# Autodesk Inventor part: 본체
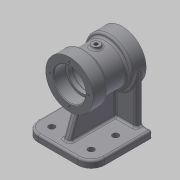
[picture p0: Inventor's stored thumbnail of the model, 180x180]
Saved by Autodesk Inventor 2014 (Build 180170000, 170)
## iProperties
Created: 2020-06
Part Number: 본체
Material: Generic
Document SubType Name: Modeling
Designer: kh
Density: 1 g/cm^3
Appearance: Default
Author: kh
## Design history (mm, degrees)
sketch "Sketch1"
  geometry: L1 (-49, -45)-(49, -45); L2 (49, -45)-(49, 45); L3 (49, 45)-(-49, 45); L4 (-49, 45)-(-49, -45); L5 (-49, -45)-(49, 45); L6 (49, -45)-(-49, 45); 1 further point
  constraints: 12 end point, 2 midpoint, 2 parallel, 1 horizontal, 1 perpendicular
  dimensions: "d0" = 98 distance of L2.end L3.end; "d1" = 90 distance of L1.end L2.end
extrude "Extrusion1" new body sketch "Sketch1" distance "d2" = 10; taper "d3" = 0 deg
workplane "Work Plane1"
sketch "Sketch2"
  geometry: L1 (49, 45)-(-49, 45) reference; L2 (-49, -45)-(49, -45) reference; L3 (0, 50)-(0, -70.604); L4 (0, 50)-(35, 50); L5 (35, 50)-(35, 28); L6 (35, 28)-(29, 28); L7 (29, 28)-(29, -6); L8 (29, -6)-(35, -6); L9 (35, -6)-(35, -28); L10 (35, -28)-(0, -28); 1 further point
  constraints: 16 end point, 5 perpendicular, 3 parallel, 1 midpoint, 1 point on line, 1 vertical alignment
  dimensions: "d5" = 5 distance from line of L1 L3.start; "d6" = 70 diameter of L5 L3; "d8" = 58 diameter of L7 L3; "d9" = 70 diameter of L9 L3; "d10" = 22 distance of L4.end L5.end; "d11" = 22 distance of L8.end L9.end; "d12" = 78 distance between parallel lines of L10 L4
revolve "Revolution1" sketch "Sketch2" stored, may be unused: angle "d13" = 90 deg
sketch "Sketch3"
  geometry: L1 (50, 115)-(50, 45) reference; L2 (-28, 115)-(-28, 45) reference; L3 (50, 80)-(-30.025, 80); L4 (50, 103.5)-(32, 103.5); L5 (32, 103.5)-(32, 100); L6 (32, 100)-(26, 100); L7 (26, 100)-(26, 103); L8 (26, 103)-(-4, 103); L9 (-4, 103)-(-4, 100); L10 (-4, 100)-(-10, 100); L11 (-10, 100)-(-10, 103.5); L12 (-10, 103.5)-(-28, 103.5); L13 (50, 103.5)-(50, 80); L14 (-28, 103.5)-(-28, 80)
  constraints: 24 end point, 7 parallel, 3 point on line, 2 collinear, 2 midpoint, 2 perpendicular
  dimensions: "d14" = 47 diameter of L4 L3; "d15" = 46 diameter of L8 L3; "d16" = 40 diameter of L6 L3; "d17" = 40 diameter of L10 L3; "d18" = 47 diameter of L12 L3; "d19" = 18 distance of L4.start L4.end; "d20" = 6 distance of L5.end L6.end; "d21" = 30 distance of L7.end L8.end; "d22" = 18 distance of L11.end L12.end
revolve "Revolution2" sketch "Sketch3" stored, may be unused: angle "d23" = 90 deg
sketch "Sketch4"
  geometry: L1 (49, 45)-(-49, 45) reference; L2 (-35, 45)-(35, 45); L3 (-35, 45)-(-35, 35); L4 (-35, 35)-(35, 35); L5 (35, 35)-(35, 45); 2 further points
  constraints: 8 end point, 2 midpoint, 2 perpendicular, 2 point on line, 1 coincident, 1 parallel
  dimensions: "d24" = 10 distance of L4.end L2.end; "d25" = 70 distance of L3.end L4.end
extrude "Extrusion2" join sketch "Sketch4" stored distance "d26" = 10; taper "d27" = 0 deg
sketch "Sketch5"
  geometry: L1 (-33, 10)-(-18.454, 49.965); L2 (45, 10)-(-45, 10) reference; L3 (-6, 45)-(-28, 45) reference
  constraints: 2 end point, 1 point on line
  dimensions: "d29" = 70 deg angle of L2 L1; "d89" = 12 distance of L2.end L1.start
feature "Rib1" sketch "Sketch5" dims "d30" = 1, "d31" = 10, "d32" = 0, "d33" = 0, "d34" = 1, "d35" = 1
sketch "Sketch6"
  geometry: C1 r 23.5 at (0, 0) reference; 1 further point
  constraints: 1 vertical alignment
  dimensions: "d36" = 28.5 distance of C1.centre point (0, -28.5)
hole "Hole1" sketch "Sketch6" at (0, -28.5) diameter "d37" = 3.242; stored, may be unused: countersink angle "d41" = 90 deg, drill point angle "d43" = 118 deg; dims "d38" = 10, "d39" = 4, "d40" = 2, "d42" = 12
pattern_circular "Circular Pattern1" dims angle "d45" = 360 deg
workplane "Work Plane2"
mirror "Mirror1"
workplane "Work Plane3"
sketch "Sketch7"
  geometry: L1 (-35, 39)-(35, 39) reference; C1 r 6 at (0, 0); 1 further point
  constraints: 1 centre point, 1 midpoint, 1 vertical alignment
  dimensions: "d47" = 39 distance from line of C1.centre L1; "d48" = 12 diameter of C1
extrude "Extrusion3" join sketch "Sketch7" stored distance "d49" = 6; taper "d50" = 0 deg
hole "Hole2" diameter "d53" = 5.188; stored, may be unused: countersink angle "d57" = 90 deg, drill point angle "d59" = 118 deg; dims "d51" = 10, "d52" = 10, "d54" = 10, "d55" = 4, "d56" = 2, "d58" = 12
sketch "Sketch8" dims "d14" = 47, "d15" = 46, "d16" = 40, "d17" = 40, "d18" = 47, "d19" = 18, "d20" = 6, "d21" = 30, "d22" = 18
  geometry: L1 (-49, 45)-(-49, -45) reference; L2 (49, -45)-(49, 45) reference; L3 (49, 45)-(35, 45) reference; 4 further points
  constraints: 2 horizontal alignment, 2 vertical alignment
  dimensions: "d60" = 70 distance from line of point (29, -25) L3; "d61" = 36 distance of point (29, 11) point (29, -25); "d64" = 20 distance from line of point (29, -25) L2; "d65" = 20 distance from line of point (-29, -25) L1
hole "Hole3" sketch "Sketch8" at (-29, -25), (-29, 11), (29, 11), (29, -25) diameter "d66" = 9; stored, may be unused: countersink angle "d70" = 90 deg, drill point angle "d72" = 118 deg; dims "d67" = 10, "d68" = 4, "d69" = 2, "d71" = 12
fillet "Fillet1" dims "d73" = 20
chamfer "Chamfer1" distance "d74" = 1; stored, may be unused: second distance "d75" = 2, angle "d76" = 45 deg
fillet "Fillet2" dims "d77" = 0.3
fillet "Fillet3" dims "d78" = 3
fillet "Fillet4" dims "d79" = 3
fillet "Fillet5" dims "d80" = 3
fillet "Fillet6" dims "d81" = 3
fillet "Fillet7" dims "d82" = 3
fillet "Fillet8" dims "d83" = 3
fillet "Fillet9" dims "d84" = 3
sketch "Sketch9"
  geometry: L1 (7, 70)-(0, 70) reference; L2 (0, 67)-(0, 70) reference; 1 further point
  constraints: 1 other
  dimensions: "d85" = 45 distance from line of point (4, 25) L1; "d86" = 4 distance from line of point (4, 25) L2
emboss "Emboss1" sketch "Sketch9" dims "d0" = 98, "d1" = 90, "d5" = 5, "d6" = 70, "d8" = 58, "d9" = 70, "d10" = 22, "d11" = 22, "d12" = 78, "d87" = 0.5, "d88" = 0
body "Solid1"
